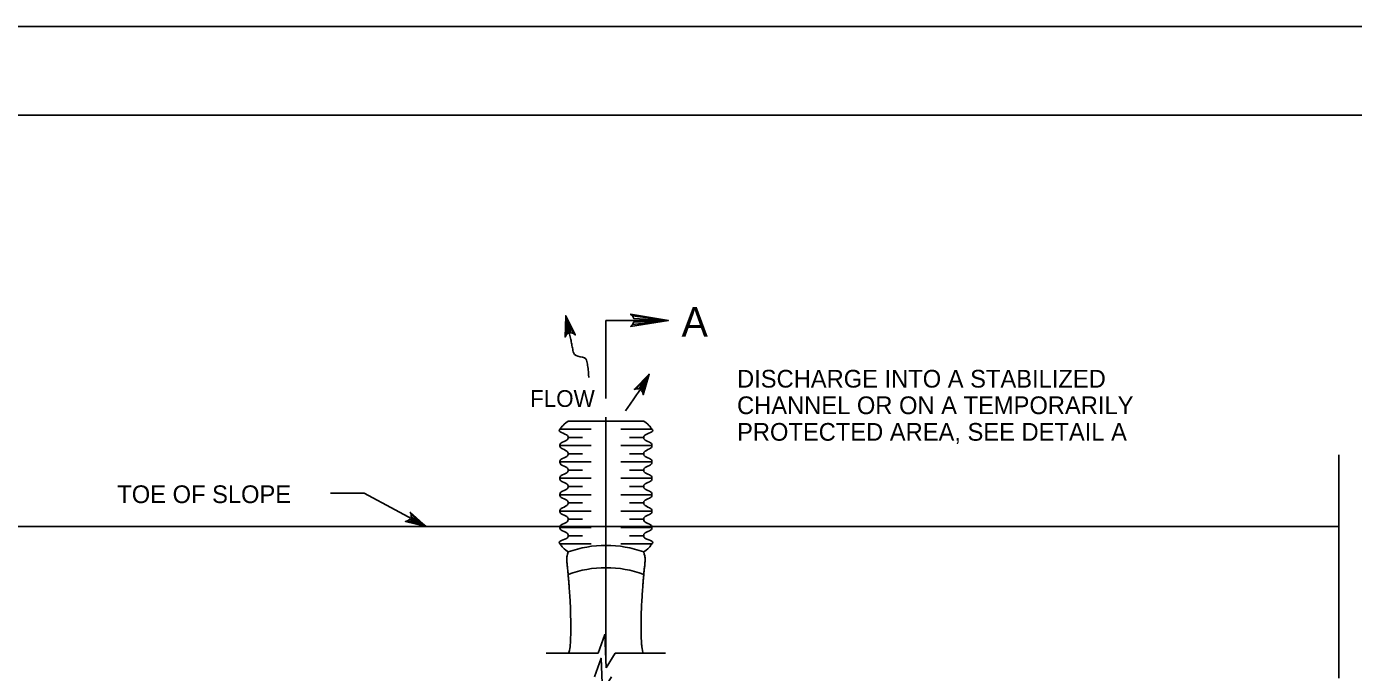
# Model space of a CAD drawing. Extents: x 636462 to 637367, y 299944 to 300538.
# Drawn here: x 636619.2 to 636843.6, y 300429.2 to 300538.4 of the extents above; entities that cross this region are included whole.
import ezdxf

# ---------------------------------------------------------------- set-up
doc = ezdxf.new("R2010")
doc.units = 0
for name, color, linetype in [('1', 7, 'Continuous'), ('Default', 7, 'Continuous'), ('PLT-BNDY', 7, 'Continuous')]:
    doc.layers.add(name, color=color, linetype=linetype)

# ---------------------------------------------------------------- blocks, each defined once
blk = doc.blocks.new('SC9446')
at = {"layer": 'Default'}
blk.add_line((0, 0), (0, 0), dxfattribs=at)

msp = doc.modelspace()

# ---------------------------------------------------------------- linework, layer by layer
at = {"layer": '1'}
msp.add_lwpolyline([(637287.91, 299959.45), (637287.91, 300523.45), (636501.91, 300523.45), (636501.91, 299959.45), (637287.91, 299959.45), (637287.91, 299985.81), (637087.91, 299985.81), (637087.91, 300050.49), (637287.91, 300050.49), (637287.91, 300079.45), (637087.91, 300079.45), (637087.91, 299959.45), (637166.72, 299959.45), (637166.72, 299985.81), (637166.72, 299959.45), (637243.72, 299959.45), (637243.72, 299985.81), (637243.72, 299973.49), (637287.91, 299973.49)], dxfattribs=at)
at = {"layer": 'Default'}
for p, q in [((636717.2, 300475.52), (636717.2, 300488.74)), ((636717.2, 300488.74), (636727.77, 300488.74)), ((636710.8, 300471.71), (636723.59, 300471.71)), ((636717.2, 300472.38), (636717.2, 300431.01)), ((636709.41, 300470.33), (636714.68, 300470.33)), ((636710.8, 300468.94), (636713.21, 300468.94)), ((636719.71, 300470.33), (636724.98, 300470.33)), ((636721.18, 300468.94), (636723.59, 300468.94)), ((636709.41, 300467.56), (636714.68, 300467.56)), ((636710.8, 300466.17), (636713.21, 300466.17)), ((636719.72, 300467.56), (636724.98, 300467.56)), ((636723.59, 300466.17), (636721.18, 300466.17)), ((636709.41, 300464.79), (636714.68, 300464.79)), ((636724.98, 300464.79), (636719.72, 300464.79)), ((636841.16, 300465.99), (636841.16, 300428.23)), ((636709.41, 300462.02), (636714.68, 300462.02)), ((636710.8, 300463.4), (636713.21, 300463.4)), ((636719.72, 300462.02), (636724.98, 300462.02)), ((636721.18, 300463.4), (636723.59, 300463.4)), ((636710.8, 300460.63), (636713.21, 300460.63)), ((636721.18, 300460.63), (636723.59, 300460.63)), ((636709.41, 300459.25), (636714.68, 300459.25)), ((636710.8, 300457.86), (636713.21, 300457.86)), ((636719.71, 300459.25), (636724.98, 300459.25)), ((636721.18, 300457.86), (636723.59, 300457.86)), ((636709.41, 300456.48), (636714.68, 300456.48)), ((636710.8, 300455.09), (636713.21, 300455.09)), ((636719.71, 300456.48), (636724.98, 300456.48)), ((636721.18, 300455.09), (636723.59, 300455.09)), ((636589.35, 300453.85), (636841.16, 300453.85)), ((636709.41, 300453.71), (636714.68, 300453.71)), ((636719.71, 300453.71), (636724.98, 300453.71)), ((636709.41, 300450.94), (636714.68, 300450.94)), ((636710.8, 300452.32), (636713.21, 300452.32)), ((636719.71, 300450.94), (636724.98, 300450.94)), ((636721.18, 300452.32), (636723.59, 300452.32)), ((636707.09, 300432.44), (636715.87, 300432.44)), ((636717.24, 300429.94), (636718.75, 300432.44)), ((636718.75, 300432.44), (636727.28, 300432.44))]:
    msp.add_line(p, q, dxfattribs=at)
for points in [[(636710.44, 300486.23), (636710.28, 300485.92), (636710.39, 300489.52), (636710.44, 300486.23), (636710.77, 300486.5), (636710.39, 300489.52), (636711.28, 300486.61), (636711.68, 300486.51), (636710.39, 300489.52), (636711.99, 300486.29), (636711.68, 300486.51)], [(636721.67, 300489.51), (636721.9, 300489.07), (636727.77, 300488.74), (636721.67, 300489.51), (636721.36, 300489.78), (636727.77, 300488.74), (636721.9, 300488.45), (636721.69, 300488.02), (636727.77, 300488.74), (636721.36, 300487.72), (636721.69, 300488.02)], [(636722.3, 300477.18), (636721.97, 300477.07), (636724.51, 300479.63), (636722.3, 300477.18), (636722.73, 300477.16), (636724.51, 300479.63), (636723.18, 300476.9), (636723.41, 300476.55), (636724.51, 300479.63), (636723.48, 300476.17), (636723.41, 300476.55)], [(636686.76, 300453.85), (636676.28, 300459.5), (636670.61, 300459.5)], [(636684.23, 300455.95), (636684.1, 300456.28), (636686.76, 300453.85), (636684.23, 300455.95), (636684.23, 300455.53), (636686.76, 300453.85), (636683.98, 300455.07), (636683.64, 300454.83), (636686.76, 300453.85), (636683.27, 300454.74), (636683.64, 300454.83)], [(636715.87, 300432.44), (636716.99, 300435.58), (636717.24, 300429.94)], [(636715.24, 300428.45), (636716.37, 300431.59), (636716.62, 300425.94), (636718.12, 300428.45)]]:
    msp.add_lwpolyline(points, dxfattribs=at)
for centre in [(636717.2, 300431.88), (636717.2, 300428.1)]:
    msp.add_arc(centre, 18.8, 70.1065, 109.8935, dxfattribs=at)
for points in [[(636714.28, 300479.06), (636714.24, 300479.88), (636714.16, 300480.69), (636714.04, 300481.5), (636713.87, 300482.58), (636711.83, 300482.62), (636711.61, 300483.68), (636711.43, 300484.49), (636711.29, 300485.31), (636711.12, 300486.12), (636710.88, 300487.25), (636710.64, 300488.39), (636710.39, 300489.52)], [(636720.52, 300473.42), (636722.87, 300476.84), (636723.26, 300477.49), (636723.67, 300478.14), (636723.97, 300478.63), (636724.16, 300479.14), (636724.51, 300479.63)], [(636710.8, 300471.71), (636710.18, 300471.25), (636709.74, 300470.79), (636709.41, 300470.33), (636709.09, 300469.87), (636710.8, 300469.4), (636710.8, 300468.94), (636710.8, 300468.48), (636709.41, 300468.02), (636709.41, 300467.56), (636709.41, 300467.1), (636710.8, 300466.64), (636710.8, 300466.17), (636710.8, 300465.71), (636709.41, 300465.25), (636709.41, 300464.79), (636709.41, 300464.33), (636710.8, 300463.87), (636710.8, 300463.4), (636710.8, 300462.94), (636709.41, 300462.48), (636709.41, 300462.02), (636709.41, 300461.56), (636710.8, 300461.1), (636710.8, 300460.63), (636710.8, 300460.17), (636709.41, 300459.71), (636709.41, 300459.25), (636709.41, 300458.79), (636710.8, 300458.33), (636710.8, 300457.86), (636710.8, 300457.4), (636709.41, 300456.94), (636709.41, 300456.48), (636709.41, 300456.02), (636710.8, 300455.56), (636710.8, 300455.09), (636710.8, 300454.63), (636709.41, 300454.17), (636709.41, 300453.71), (636709.41, 300453.25), (636710.8, 300452.79), (636710.8, 300452.32), (636710.8, 300451.86), (636709.09, 300451.4), (636709.41, 300450.94), (636709.74, 300450.48), (636710.18, 300450.02), (636710.8, 300449.56)], [(636723.59, 300471.71), (636724.21, 300471.25), (636724.65, 300470.79), (636724.98, 300470.33), (636725.31, 300469.87), (636723.59, 300469.4), (636723.59, 300468.94), (636723.59, 300468.48), (636724.98, 300468.02), (636724.98, 300467.56), (636724.98, 300467.1), (636723.59, 300466.64), (636723.59, 300466.17), (636723.59, 300465.71), (636724.98, 300465.25), (636724.98, 300464.79), (636724.98, 300464.33), (636723.59, 300463.87), (636723.59, 300463.4), (636723.59, 300462.94), (636724.98, 300462.48), (636724.98, 300462.02), (636724.98, 300461.56), (636723.59, 300461.1), (636723.59, 300460.63), (636723.59, 300460.17), (636724.98, 300459.71), (636724.98, 300459.25), (636724.98, 300458.79), (636723.59, 300458.33), (636723.59, 300457.86), (636723.59, 300457.4), (636724.98, 300456.94), (636724.98, 300456.48), (636724.98, 300456.02), (636723.59, 300455.56), (636723.59, 300455.09), (636723.59, 300454.63), (636724.98, 300454.17), (636724.98, 300453.71), (636724.98, 300453.25), (636723.59, 300452.79), (636723.59, 300452.32), (636723.59, 300451.86), (636725.31, 300451.4), (636724.98, 300450.94), (636724.65, 300450.48), (636724.21, 300450.02), (636723.59, 300449.56)], [(636710.8, 300449.56), (636710.66, 300449.03), (636710.54, 300448.5), (636710.58, 300447.97), (636710.64, 300447.24), (636710.74, 300446.51), (636710.8, 300445.78), (636710.86, 300445.04), (636710.92, 300444.3), (636710.97, 300443.56), (636711.05, 300442.55), (636711.12, 300441.54), (636711.17, 300440.53), (636711.23, 300439.52), (636711.22, 300438.51), (636711.24, 300437.5), (636711.26, 300436.34), (636711.23, 300435.17), (636711.17, 300434.01), (636711.14, 300433.51), (636710.86, 300432.07), (636710.84, 300432.56)], [(636723.59, 300449.56), (636723.73, 300449.03), (636723.86, 300448.5), (636723.81, 300447.97), (636723.76, 300447.24), (636723.65, 300446.51), (636723.59, 300445.78), (636723.53, 300445.04), (636723.47, 300444.3), (636723.42, 300443.56), (636723.34, 300442.55), (636723.28, 300441.54), (636723.22, 300440.53), (636723.17, 300439.52), (636723.17, 300438.51), (636723.16, 300437.5), (636723.14, 300436.34), (636723.16, 300435.17), (636723.22, 300434.01), (636723.25, 300433.51), (636723.54, 300432.07), (636723.55, 300432.56)]]:
    msp.add_open_spline(points, degree=3, dxfattribs=at)
at = {"layer": 'PLT-BNDY'}
msp.add_lwpolyline([(636461.91, 300538.45), (637302.91, 300538.45), (637302.91, 299944.45), (636461.91, 299944.45)], close=True, dxfattribs=at)

# ---------------------------------------------------------------- block references
at = {"layer": 'Default', "xscale": 2.753831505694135, "yscale": 2.753831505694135}
msp.add_blockref('SC9446', (636714.68, 300464.79), dxfattribs=at)

# ---------------------------------------------------------------- texts
at = {"layer": 'Default'}
for s, height, p in [('A', 5, (636729.98, 300485.98)), ('DISCHARGE INTO A STABILIZED', 2.998, (636739.37, 300477.37)), ('FLOW', 2.835, (636704.35, 300474.1)), ('CHANNEL OR ON A TEMPORARILY', 2.998, (636739.37, 300472.88)), ('PROTECTED AREA, SEE DETAIL A', 2.998, (636739.37, 300468.38)), ('TOE OF SLOPE', 2.998, (636634.54, 300457.83))]:
    msp.add_text(s, height=height, dxfattribs=at).set_placement(p)

doc.saveas('drawing.dxf')
